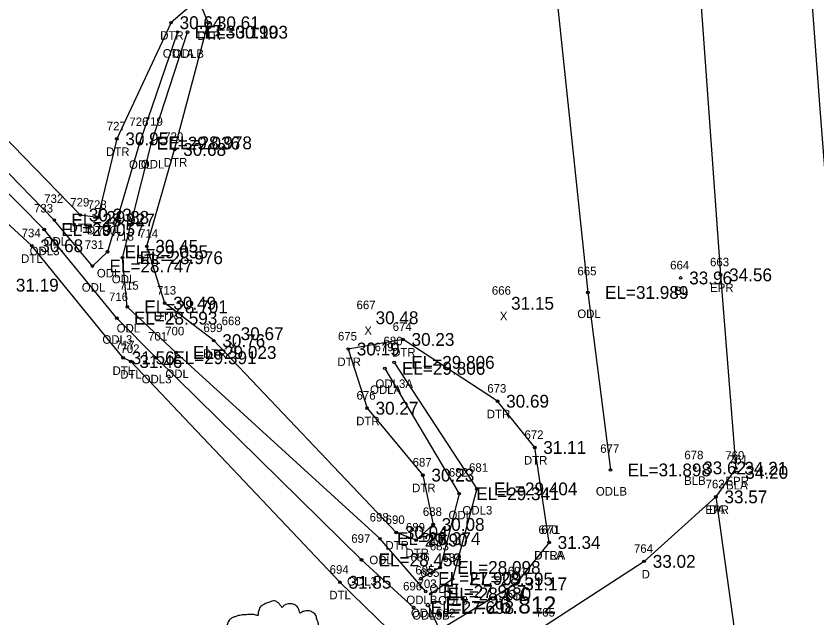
# Model space of a CAD drawing. Extents: x 2042117 to 2045853, y 303080 to 309569.
# Drawn here: x 2042751.6 to 2042845.4, y 307140.2 to 307210.7 of the extents above; entities that cross this region are included whole.
import ezdxf

# ---------------------------------------------------------------- set-up
doc = ezdxf.new("R2010")
doc.units = 0
for name, color, linetype in [('RD_DTM_BkLn_txCode', 7, 'Continuous'), ('RD_EX_DR_Pipe', 7, 'Continuous'), ('RD_EX_DR_Pipe_txCode', 7, 'Continuous'), ('RD_EX_Driveway', 7, 'Continuous'), ('RD_EX_Driveway_txCode', 7, 'Continuous'), ('RD_EX_H2O', 7, 'Continuous'), ('RD_EX_H2O_txCode', 7, 'Continuous'), ('RD_EX_Misc_txCode', 7, 'Continuous'), ('RD_EX_Road', 7, 'Continuous'), ('RD_EX_Road_txCode', 7, 'Continuous'), ('RD_EX_TX_Driveway_ELEV', 7, 'Continuous'), ('RD_EX_TX_H2O_ELEV', 7, 'Continuous'), ('RD_EX_TX_Misc_ELEV', 7, 'Continuous'), ('RD_EX_TX_Road_ELEV', 7, 'Continuous'), ('RD_EX_VEG', 7, 'Continuous'), ('RD_HC_Cl', 7, 'Continuous'), ('RD_SMD_Locator', 7, 'Continuous'), ('RD_TX_Pipe_ElevEX', 7, 'Continuous')]:
    doc.layers.add(name, color=color, linetype=linetype)

msp = doc.modelspace()

# ---------------------------------------------------------------- linework, layer by layer
at = {"layer": 'RD_EX_DR_Pipe'}
msp.add_line((2042799.852, 307141.729), (2042810.843, 307118.409), dxfattribs=at)
at = {"layer": 'RD_EX_Driveway'}
msp.add_lwpolyline([(2042833.55, 307154.384), (2042825.159, 307146.837), (2042813.676, 307139.379), (2042805.118, 307136.689), (2042787.057, 307130.546), (2042752.791, 307124.242)], dxfattribs=at)
at = {"layer": 'RD_EX_H2O'}
for points in [[(2042809.034, 307329.141), (2042809.101, 307278.692), (2042813.163, 307229.385), (2042818.569, 307178.306), (2042821.216, 307157.54)], [(2042814.027, 307149.05), (2042810.112, 307144.206), (2042802.017, 307139.291), (2042796.625, 307137.517), (2042789.542, 307144.391), (2042765.069, 307170.219), (2042764.169, 307170.659), (2042753.465, 307183.772), (2042731.919, 307203.607), (2042715.016, 307220.147), (2042682.706, 307253.516), (2042652.804, 307280.333), (2042645.058, 307288.416)], [(2042798.162, 307141.437), (2042792.071, 307147.012), (2042768.023, 307170.668), (2042763.43, 307175.3), (2042754.912, 307185.665), (2042734.729, 307206.069), (2042717.18, 307221.145), (2042685.329, 307255.34), (2042657.065, 307284.58)], [(2042770.538, 307208.776), (2042766.098, 307195.775), (2042762.333, 307183.062), (2042760.565, 307181.394), (2042756.105, 307186.782), (2042736.262, 307207.113), (2042718.537, 307222.325), (2042687.24, 307256.919), (2042685.675, 307258.5)], [(2042814.027, 307149.05), (2042812.345, 307160.168), (2042807.995, 307165.577), (2042796.924, 307172.805), (2042790.514, 307171.687), (2042792.711, 307164.761), (2042799.253, 307156.934), (2042800.452, 307151.156), (2042798.465, 307149.319), (2042796.137, 307150.217), (2042774.771, 307172.667), (2042769.031, 307177.057), (2042766.927, 307183.712), (2042770.194, 307195.04), (2042774.132, 307209.863), (2042772.991, 307212.659), (2042769.772, 307209.877), (2042763.427, 307196.276), (2042761.186, 307187.089), (2042759.154, 307187.365), (2042738.043, 307209.089), (2042720.637, 307223.823), (2042688.551, 307257.732)], [(2042799.58, 307143.305), (2042794.228, 307149.499), (2042770.351, 307171.286), (2042764.65, 307176.624), (2042764.081, 307182.37), (2042767.479, 307195.816), (2042771.696, 307208.761)], [(2042795.887, 307170.125), (2042805.575, 307155.319), (2042802.726, 307144.771), (2042800.163, 307143.026)], [(2042794.799, 307169.425), (2042803.495, 307154.751), (2042801.269, 307146.129), (2042799.033, 307144.831)]]:
    msp.add_lwpolyline(points, dxfattribs=at)
at = {"layer": 'RD_EX_Road'}
msp.add_lwpolyline([(2042828.357, 307428.87), (2042826.994, 307378.911), (2042826.878, 307329.287), (2042828.013, 307279.816), (2042830.497, 307230.241), (2042834.094, 307180.367), (2042835.887, 307157.733), (2042833.55, 307154.384), (2042836.54, 307132.831), (2042837.327, 307130.114), (2042837.641, 307128.77), (2042839.219, 307126.163), (2042844.982, 307081.334), (2042852.857, 307032.13), (2042861.739, 306982.988), (2042871.664, 306934.616), (2042883.382, 306885.882), (2042895.938, 306837.564), (2042909.761, 306789.886)], dxfattribs=at)
at = {"layer": 'RD_EX_VEG'}
for points in [[(2042782.045, 307142.191), (2042781.746, 307142.216), (2042781.421, 307142.116), (2042781.171, 307142.016), (2042780.946, 307141.941), (2042780.721, 307141.841), (2042780.421, 307141.666), (2042780.196, 307141.466), (2042780.071, 307141.216), (2042780.021, 307140.991), (2042779.971, 307140.716), (2042779.971, 307140.541), (2042779.846, 307140.516), (2042779.696, 307140.541), (2042779.447, 307140.616), (2042779.197, 307140.616), (2042778.947, 307140.616), (2042778.597, 307140.591), (2042778.247, 307140.591), (2042777.972, 307140.541), (2042777.647, 307140.492), (2042777.273, 307140.367), (2042776.923, 307140.242), (2042776.623, 307139.992), (2042776.373, 307139.517), (2042776.248, 307139.167), (2042776.098, 307138.917), (2042776.248, 307138.467), (2042776.423, 307138.118), (2042776.448, 307137.918), (2042776.523, 307137.493), (2042776.623, 307137.268), (2042776.748, 307137.068), (2042776.673, 307137.043), (2042776.298, 307136.993), (2042775.998, 307136.893), (2042775.573, 307136.668), (2042775.348, 307136.443), (2042775.248, 307136.118), (2042775.223, 307135.769), (2042775.124, 307135.569), (2042775.049, 307135.294), (2042775.024, 307135.219), (2042774.974, 307134.894), (2042775.074, 307134.444), (2042775.099, 307134.094), (2042775.223, 307133.869), (2042775.373, 307133.695), (2042775.548, 307133.445), (2042775.948, 307133.22), (2042776.273, 307133.12), (2042776.473, 307133.095), (2042776.298, 307132.595), (2042776.248, 307132.245), (2042776.123, 307131.845), (2042776.123, 307131.77), (2042776.073, 307131.296), (2042776.223, 307130.971), (2042776.298, 307130.596), (2042776.473, 307130.371), (2042776.748, 307130.071), (2042777.073, 307129.846), (2042777.572, 307129.721), (2042777.972, 307129.746), (2042778.547, 307129.921), (2042778.797, 307129.996), (2042778.772, 307129.821), (2042778.797, 307129.446), (2042778.797, 307129.022), (2042778.947, 307128.697), (2042779.047, 307128.422), (2042779.197, 307128.172), (2042779.522, 307127.947), (2042779.921, 307127.872), (2042780.346, 307127.722), (2042780.796, 307127.647), (2042781.296, 307127.622), (2042781.896, 307127.772), (2042782.17, 307127.897), (2042782.27, 307128.072), (2042782.47, 307128.447), (2042782.42, 307128.672), (2042782.445, 307129.271), (2042782.545, 307129.096), (2042782.72, 307128.747), (2042783.22, 307128.447), (2042783.62, 307128.272), (2042784.095, 307128.122), (2042784.394, 307128.047), (2042784.869, 307128.122), (2042785.244, 307128.197), (2042785.619, 307128.322), (2042785.919, 307128.597), (2042786.094, 307128.872), (2042786.144, 307129.146), (2042786.219, 307129.521), (2042786.269, 307129.696)], [(2042786.269, 307129.696), (2042786.194, 307129.871), (2042786.144, 307130.121), (2042786.219, 307130.096), (2042786.394, 307130.046), (2042786.668, 307129.921), (2042786.893, 307129.846), (2042787.218, 307129.871), (2042787.493, 307129.971), (2042787.943, 307130.246), (2042788.218, 307130.721), (2042788.493, 307131.121), (2042788.568, 307131.445), (2042788.518, 307131.67), (2042788.493, 307132.17), (2042788.293, 307132.42), (2042788.243, 307132.545), (2042788.143, 307132.945), (2042788.218, 307132.995), (2042788.493, 307133.045), (2042788.867, 307133.17), (2042789.142, 307133.295), (2042789.367, 307133.47), (2042789.442, 307133.695), (2042789.417, 307134.094), (2042789.467, 307134.494), (2042789.392, 307134.644), (2042789.292, 307134.794), (2042789.217, 307134.994), (2042789.067, 307135.144), (2042788.967, 307135.294), (2042788.867, 307135.394), (2042788.743, 307135.544), (2042788.568, 307135.669), (2042788.418, 307135.719), (2042788.368, 307135.869), (2042788.518, 307136.068), (2042788.568, 307136.168), (2042788.593, 307136.393), (2042788.818, 307136.743), (2042788.867, 307137.143), (2042788.818, 307137.568), (2042788.768, 307137.843), (2042788.618, 307138.118), (2042788.418, 307138.367), (2042788.293, 307138.542), (2042788.118, 307138.667), (2042787.793, 307138.792), (2042787.543, 307138.842), (2042787.193, 307138.842), (2042786.993, 307138.892), (2042787.018, 307138.942), (2042787.018, 307139.092), (2042787.018, 307139.367), (2042786.943, 307139.817), (2042786.793, 307140.317), (2042786.793, 307140.342), (2042786.693, 307140.591), (2042786.469, 307140.791), (2042786.294, 307140.891), (2042786.094, 307141.016), (2042785.844, 307141.041), (2042785.544, 307141.041), (2042785.269, 307140.991), (2042785.069, 307140.891), (2042784.894, 307140.766), (2042784.819, 307140.916), (2042784.719, 307141.216), (2042784.669, 307141.366), (2042784.519, 307141.541), (2042784.295, 307141.741), (2042783.845, 307141.866), (2042783.22, 307141.791), (2042782.92, 307141.591), (2042782.77, 307141.416), (2042782.72, 307141.541), (2042782.52, 307141.741), (2042782.42, 307141.916), (2042782.245, 307142.041), (2042782.095, 307142.141), (2042781.995, 307142.191)]]:
    msp.add_spline(points, degree=3, dxfattribs=at)
at = {"layer": 'RD_HC_Cl'}
msp.add_arc((2044751.247, 307348.431), 1911.291, 137.681845, 219.868361, dxfattribs=at)
at = {"layer": 'RD_SMD_Locator'}
for centre, radius in [((2042769.772, 307209.877), 0.15), ((2042774.132, 307209.863), 0.15), ((2042770.538, 307208.776), 0.15), ((2042771.696, 307208.761), 0.15), ((2042763.427, 307196.276), 0.15), ((2042766.098, 307195.775), 0.15), ((2042767.479, 307195.816), 0.15), ((2042770.194, 307195.04), 0.15), ((2042759.154, 307187.365), 0.15), ((2042756.105, 307186.782), 0.15), ((2042761.186, 307187.089), 0.15), ((2042754.912, 307185.665), 0.15), ((2042753.465, 307183.772), 0.15), ((2042766.927, 307183.712), 0.15), ((2042762.333, 307183.062), 0.15), ((2042764.081, 307182.37), 0.15), ((2042760.565, 307181.394), 0.15), ((2042829.424, 307180.004), 0.15), ((2042834.094, 307180.367), 0.15), ((2042818.569, 307178.306), 0.15), ((2042769.031, 307177.057), 0.15), ((2042764.65, 307176.624), 0.15), ((2042763.43, 307175.3), 0.15), ((2042774.771, 307172.667), 0.15), ((2042796.924, 307172.805), 0.15), ((2042770.351, 307171.286), 0.15), ((2042790.514, 307171.687), 0.15), ((2042764.169, 307170.659), 0.15), ((2042768.023, 307170.668), 0.15), ((2042765.069, 307170.219), 0.15), ((2042794.799, 307169.425), 0.15), ((2042795.887, 307170.125), 0.15), ((2042792.711, 307164.761), 0.15), ((2042807.995, 307165.577), 0.15), ((2042812.345, 307160.168), 0.15), ((2042821.216, 307157.54), 0.15), ((2042831.063, 307157.785), 0.15), ((2042835.887, 307157.733), 0.15), ((2042835.989, 307157.254), 0.15), ((2042799.253, 307156.934), 0.15), ((2042803.495, 307154.751), 0.15), ((2042805.575, 307155.319), 0.15), ((2042833.55, 307154.384), 0.15), ((2042833.55, 307154.384), 0.15), ((2042800.452, 307151.156), 0.15), ((2042796.137, 307150.217), 0.15), ((2042794.228, 307149.499), 0.15), ((2042798.465, 307149.319), 0.15), ((2042814.027, 307149.05), 0.15), ((2042814.027, 307149.05), 0.15), ((2042792.071, 307147.012), 0.15), ((2042801.269, 307146.129), 0.15), ((2042825.159, 307146.837), 0.15), ((2042789.542, 307144.391), 0.15), ((2042799.033, 307144.831), 0.15), ((2042802.726, 307144.771), 0.15), ((2042810.112, 307144.206), 0.15), ((2042799.58, 307143.305), 0.15), ((2042800.163, 307143.026), 0.15), ((2042798.162, 307141.437), 0.15), ((2042799.852, 307141.729), 0.2)]:
    msp.add_circle(centre, radius, dxfattribs=at)

# ---------------------------------------------------------------- texts
at = {"layer": 'RD_DTM_BkLn_txCode'}
for s, p in [('664', (2042828.196, 307181.004)), ('BL', (2042828.668, 307178.004)), ('678', (2042829.858, 307158.785)), ('761', (2042835.068, 307158.254)), ('BLB', (2042829.835, 307155.785)), ('BLA', (2042834.745, 307155.254))]:
    msp.add_text(s, height=1, dxfattribs=at).set_placement(p)
at = {"layer": 'RD_EX_DR_Pipe_txCode'}
msp.add_text('703', height=1, dxfattribs=at).set_placement((2042798.631, 307143.729))
at = {"layer": 'RD_EX_Driveway_txCode'}
for s, p in [('763', (2042832.346, 307155.384)), ('DA', (2042832.755, 307152.384)), ('764', (2042823.954, 307147.837)), ('D', (2042824.852, 307144.837)), ('765', (2042812.471, 307140.379))]:
    msp.add_text(s, height=1, dxfattribs=at).set_placement(p)
at = {"layer": 'RD_EX_H2O_txCode'}
for s, p in [('DTR', (2042768.504, 307207.877)), ('DTR', (2042772.864, 307207.863)), ('ODLA', (2042768.805, 307205.776)), ('ODLB', (2042769.98, 307205.761)), ('726', (2042764.893, 307197.775)), ('719', (2042766.581, 307197.816)), ('727', (2042762.246, 307197.276)), ('720', (2042768.974, 307196.04)), ('DTR', (2042762.159, 307194.276)), ('DTR', (2042768.926, 307193.04)), ('ODL', (2042764.853, 307192.775)), ('ODL', (2042766.235, 307192.816)), ('732', (2042754.924, 307188.782)), ('729', (2042757.973, 307188.365)), ('733', (2042753.731, 307187.665)), ('728', (2042760.005, 307188.089)), ('734', (2042752.284, 307184.772)), ('DTR', (2042757.886, 307185.365)), ('DTR', (2042759.919, 307185.089)), ('730', (2042761.113, 307185.062)), ('714', (2042766.029, 307184.712)), ('ODL', (2042754.861, 307183.782)), ('718', (2042763.183, 307184.37)), ('ODL3', (2042753.219, 307182.665)), ('731', (2042759.668, 307183.394)), ('DTL', (2042752.221, 307181.772)), ('DTR', (2042765.659, 307181.712)), ('ODL', (2042761.089, 307180.062)), ('665', (2042817.341, 307180.306)), ('ODL', (2042762.837, 307179.37)), ('ODL', (2042759.321, 307178.394)), ('715', (2042763.752, 307178.624)), ('713', (2042768.133, 307178.057)), ('716', (2042762.509, 307177.3)), ('ODL', (2042817.325, 307175.306)), ('DTR', (2042767.763, 307175.057)), ('ODL', (2042763.406, 307173.624)), ('700', (2042769.091, 307173.286)), ('699', (2042773.567, 307173.667)), ('674', (2042795.719, 307173.805)), ('ODL3', (2042761.737, 307172.3)), ('701', (2042767.086, 307172.668)), ('675', (2042789.309, 307172.687)), ('717', (2042763.271, 307171.659)), ('679', (2042793.595, 307171.425)), ('680', (2042794.643, 307172.125)), ('702', (2042763.849, 307171.219)), ('DTR', (2042773.504, 307170.667)), ('DTR', (2042795.656, 307170.805)), ('DTR', (2042789.246, 307169.687)), ('DTL', (2042762.925, 307168.659)), ('DTL', (2042763.825, 307168.219)), ('ODL3', (2042766.33, 307167.668)), ('ODL', (2042769.107, 307168.286)), ('ODL3A', (2042793.705, 307167.125)), ('676', (2042791.483, 307165.761)), ('ODLA', (2042793.067, 307166.425)), ('673', (2042806.79, 307166.577)), ('DTR', (2042806.727, 307163.577)), ('DTR', (2042791.443, 307162.761)), ('672', (2042811.141, 307161.168)), ('677', (2042820.011, 307159.54)), ('687', (2042798.048, 307157.934)), ('681', (2042804.654, 307157.319)), ('DTR', (2042811.078, 307158.168)), ('682', (2042802.29, 307156.751)), ('DTR', (2042797.985, 307154.934)), ('ODLB', (2042819.5, 307154.54)), ('688', (2042799.247, 307152.156)), ('ODL', (2042802.251, 307151.751)), ('ODL3', (2042803.882, 307152.319)), ('698', (2042793.023, 307151.499)), ('690', (2042794.893, 307151.217)), ('689', (2042797.261, 307150.319)), ('670', (2042812.783, 307150.05)), ('671', (2042813.105, 307150.05)), ('697', (2042790.866, 307149.012)), ('DTR', (2042799.184, 307149.156)), ('DTR', (2042794.869, 307148.217)), ('683', (2042800.065, 307148.129)), ('DTR', (2042797.198, 307147.319)), ('DTRA', (2042812.271, 307147.05)), ('DTLA', (2042812.294, 307147.05)), ('ODL', (2042792.984, 307146.499)), ('686', (2042797.805, 307146.831)), ('684', (2042801.521, 307146.771)), ('694', (2042788.337, 307145.391)), ('695', (2042798.375, 307145.305)), ('691', (2042809.19, 307145.206)), ('685', (2042798.958, 307145.026)), ('ODL3', (2042790.378, 307144.012)), ('696', (2042796.934, 307143.437)), ('DTL', (2042788.298, 307142.391)), ('ODL', (2042800.025, 307143.129)), ('ODLB', (2042797.317, 307141.831)), ('ODL3', (2042801.033, 307141.771)), ('DTL', (2042808.867, 307142.206)), ('ODLA', (2042797.848, 307140.305)), ('ODL3B', (2042797.998, 307140.026)), ('692', (2042800.812, 307140.291))]:
    msp.add_text(s, height=1, dxfattribs=at).set_placement(p)
at = {"layer": 'RD_EX_Misc_txCode'}
for s, p in [('666', (2042807.324, 307178.039)), ('667', (2042791.485, 307176.349)), ('668', (2042775.695, 307174.48)), ('X', (2042808.261, 307175.039)), ('X', (2042792.398, 307173.349)), ('X', (2042776.609, 307171.48))]:
    msp.add_text(s, height=1, dxfattribs=at).set_placement(p)
at = {"layer": 'RD_EX_Road_txCode'}
for s, p in [('663', (2042832.866, 307181.367)), ('EPR', (2042832.866, 307178.367)), ('760', (2042834.643, 307158.733)), ('EPR', (2042834.658, 307155.733)), ('762', (2042832.346, 307155.384)), ('EPR', (2042832.322, 307152.384))]:
    msp.add_text(s, height=1, dxfattribs=at).set_placement(p)
at = {"layer": 'RD_EX_TX_Driveway_ELEV'}
for s, p in [('33.57', (2042834.55, 307153.634)), ('33.02', (2042826.159, 307146.087))]:
    msp.add_text(s, height=1.5, dxfattribs=at).set_placement(p)
at = {"layer": 'RD_EX_TX_H2O_ELEV'}
for s, p in [('30.64', (2042770.772, 307209.127)), ('30.61', (2042775.132, 307209.113)), ('EL=30.199', (2042772.538, 307208.026)), ('EL=30.103', (2042773.696, 307208.011)), ('30.95', (2042764.427, 307195.526)), ('EL=29.036', (2042768.098, 307195.025)), ('EL=28.978', (2042769.479, 307195.066)), ('30.68', (2042771.194, 307194.29)), ('EL=28.927', (2042758.105, 307186.032)), ('30.23', (2042760.154, 307186.615)), ('29.88', (2042762.186, 307186.339)), ('EL=29.057', (2042756.912, 307184.915)), ('30.68', (2042754.465, 307183.022)), ('EL=29.035', (2042764.333, 307182.312)), ('30.45', (2042767.927, 307182.962)), ('EL=28.976', (2042766.081, 307181.62)), ('EL=28.747', (2042762.565, 307180.644)), ('EL=31.989', (2042820.569, 307177.556)), ('EL=28.701', (2042766.65, 307175.874)), ('30.49', (2042770.031, 307176.307)), ('EL=28.593', (2042765.43, 307174.55)), ('30.76', (2042775.771, 307171.917)), ('30.23', (2042797.924, 307172.055)), ('30.19', (2042791.514, 307170.937)), ('31.56', (2042765.169, 307169.909)), ('EL=29.391', (2042770.023, 307169.918)), ('EL=29.023', (2042772.351, 307170.536)), ('31.46', (2042766.069, 307169.469)), ('EL=29.806', (2042797.887, 307169.375)), ('EL=29.806', (2042796.799, 307168.675)), ('30.69', (2042808.995, 307164.827)), ('30.27', (2042793.711, 307164.011)), ('31.11', (2042813.345, 307159.418)), ('EL=31.898', (2042823.216, 307156.79)), ('30.23', (2042800.253, 307156.184)), ('EL=29.341', (2042805.495, 307154.001)), ('EL=29.404', (2042807.575, 307154.569)), ('30.08', (2042801.452, 307150.406)), ('30.04', (2042797.137, 307149.467)), ('EL=28.374', (2042796.228, 307148.749)), ('29.90', (2042799.465, 307148.569)), ('31.34', (2042815.027, 307148.3)), ('31.34', (2042815.027, 307148.3)), ('EL=28.458', (2042794.071, 307146.262)), ('EL=28.098', (2042803.269, 307145.379)), ('EL=27.909', (2042801.033, 307144.081)), ('EL=28.595', (2042804.726, 307144.021)), ('31.85', (2042790.542, 307143.641)), ('31.17', (2042811.112, 307143.456)), ('EL=27.967', (2042801.58, 307142.555)), ('EL=28.180', (2042802.163, 307142.276)), ('EL=27.698', (2042800.162, 307140.687))]:
    msp.add_text(s, height=1.5, dxfattribs=at).set_placement(p)
at = {"layer": 'RD_EX_TX_Misc_ELEV'}
for s, p in [('31.19', (2042751.602, 307178.413)), ('33.96', (2042830.424, 307179.254)), ('31.15', (2042809.576, 307176.289)), ('30.48', (2042793.713, 307174.599)), ('30.67', (2042777.924, 307172.73)), ('33.62', (2042832.063, 307157.035)), ('34.20', (2042836.989, 307156.504))]:
    msp.add_text(s, height=1.5, dxfattribs=at).set_placement(p)
at = {"layer": 'RD_EX_TX_Road_ELEV'}
for s, p in [('34.56', (2042835.094, 307179.617)), ('34.21', (2042836.887, 307156.983)), ('33.57', (2042834.55, 307153.634))]:
    msp.add_text(s, height=1.5, dxfattribs=at).set_placement(p)
at = {"layer": 'RD_TX_Pipe_ElevEX'}
msp.add_text('EL=26.812', height=2, dxfattribs=at).set_placement((2042801.852, 307140.729))

doc.saveas('drawing.dxf')
